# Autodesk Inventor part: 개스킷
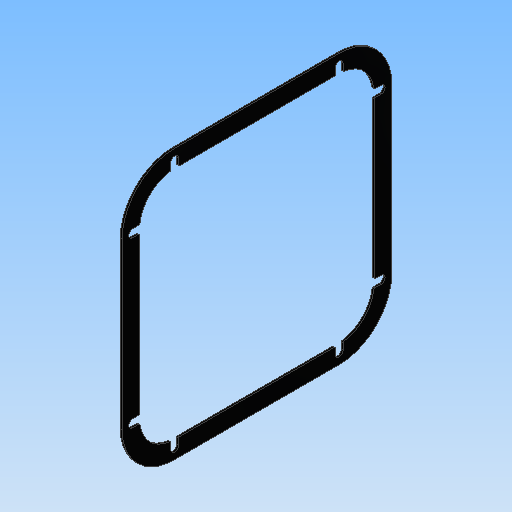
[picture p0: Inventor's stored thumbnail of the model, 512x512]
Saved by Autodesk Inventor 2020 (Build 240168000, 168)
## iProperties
Created: 2022-02
Part Number: 개스킷
Material: 황동, 연질 노란색
Document SubType Name: Modeling
Designer: mdu-edu
Density: 8.47 g/cm^3
Mass: 43.3806 g
Surface Area: 113.92 cm^2
Volume: 5.12167 cm^3
Appearance: 피막 처리 - 검은색
Author: mdu-edu
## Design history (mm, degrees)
sketch "스케치1"
  geometry: L1 (-77, 77)-(77, 77); L2 (77, 77)-(77, -77); L3 (77, -77)-(-77, -77); L4 (-77, -77)-(-77, 77); L5 (-77, 77)-(77, -77); L6 (77, 77)-(-77, -77); 1 further point
  constraints: 12 end point, 2 midpoint, 2 parallel, 2 perpendicular, 1 horizontal
  dimensions: "d1" = 154 distance of L1.end L2.end
extrude "돌출1" new body sketch "스케치1" distance "d2" = 1; taper "d3" = 0 deg
fillet "모깎기1" dims "d4" = 30
sketch "스케치2"
  geometry: L1 (-47, -77)-(47, -77) reference; L2 (77, -47)-(77, 47) reference; L3 (47, 77)-(-47, 77) reference; L4 (-77, 47)-(-77, -47) reference; L5 (67, 47)-(67, -47); L6 (47, -67)-(-47, -67); L7 (-67, -47)-(-67, 47); L8 (-47, 67)-(47, 67); A1 r 30 centre (-47, -47) between (-77, -47) and (-47, -77) reference; A2 r 30 centre (47, -47) between (47, -77) and (77, -47) reference; A3 r 30 centre (47, 47) between (77, 47) and (47, 77) reference; A4 r 30 centre (-47, 47) between (-47, 77) and (-77, 47) reference; A5 r 20 centre (47, 47) between (67, 47) and (47, 67); A6 r 20 centre (47, -47) between (47, -67) and (67, -47); A7 r 20 centre (-47, -47) between (-67, -47) and (-47, -67); A8 r 20 centre (-47, 47) between (-47, 67) and (-67, 47); 1 further point
  constraints: 8 end point, 8 point on circle, 4 centre point, 7 other
  dimensions: "d5" = 10 distance between parallel lines of L2 L5
extrude "돌출2" cut sketch "스케치2" extent not by distance; stored distance "d6" = 1; taper "d7" = 0 deg
sketch "스케치3"
  geometry: L1 (47, 77)-(-47, 77) reference; L2 (77, -47)-(77, 47) reference; L3 (-47, -77)-(47, -77) reference; L4 (-77, 47)-(-77, -47) reference; L5 (-47, 71)-(47, 71); L6 (71, 47)-(71, -47); L7 (47, -71)-(-47, -71); L8 (-71, -47)-(-71, 47); A1 r 30 centre (47, 47) between (77, 47) and (47, 77) reference; A2 r 30 centre (47, -47) between (47, -77) and (77, -47) reference; A3 r 30 centre (-47, -47) between (-77, -47) and (-47, -77) reference; A4 r 30 centre (-47, 47) between (-47, 77) and (-77, 47) reference; A5 r 24 centre (47, 47) between (71, 47) and (47, 71); A6 r 24 centre (47, -47) between (47, -71) and (71, -47); A7 r 24 centre (-47, -47) between (-71, -47) and (-47, -71); A8 r 24 centre (-47, 47) between (-47, 71) and (-71, 47); 9 further points
  constraints: 8 coincident, 8 end point, 8 point on circle, 4 centre point, 7 other
  dimensions: "d8" = 6 distance between parallel lines of L2 L6
hole "구멍1" sketch "스케치3" at (-47, 71), (47, 71), (71, 47), (71, -47), (47, -71), (-47, -71), (-71, -47), (-71, 47) diameter "d9" = 4.5; stored, may be unused: countersink angle "d13" = 90 deg, drill point angle "d15" = 118 deg; dims "d10" = 6, "d11" = 4, "d12" = 2, "d14" = 8
sketch "스케치4"
  geometry: L1 (-47, 67)-(47, 67) reference; L2 (-67, -47)-(-67, 47) reference; L3 (67, 47)-(67, -47) reference; L4 (47, -67)-(-47, -67) reference; L5 (-44.75, 71)-(-44.75, 67); L6 (-49.25, 71)-(-49.25, 66.873); L7 (-71, 49.25)-(-66.873, 49.25); L8 (-71, 44.75)-(-67, 44.75); L9 (0, 0)-(0, 67); L10 (0, 0)-(-67, 0); L11 (49.25, 71)-(49.25, 66.873); L12 (44.75, 71)-(44.75, 67); L13 (71, 49.25)-(66.873, 49.25); L14 (71, 44.75)-(67, 44.75); L15 (-44.75, -71)-(-44.75, -67); L16 (-49.25, -71)-(-49.25, -66.873); L17 (-71, -49.25)-(-66.873, -49.25); L18 (-71, -44.75)-(-67, -44.75); L19 (49.25, -71)-(49.25, -66.873); L20 (44.75, -71)-(44.75, -67); L21 (71, -49.25)-(66.873, -49.25); L22 (71, -44.75)-(67, -44.75); C1 r 2.25 at (47, 71) reference; C2 r 2.25 at (71, 47) reference; C3 r 2.25 at (71, -47) reference; C4 r 2.25 at (47, -71) reference; C5 r 2.25 at (-47, -71) reference; C6 r 2.25 at (-71, -47) reference; A1 r 2.25 centre (-47, 71) between (-44.75, 71) and (-49.25, 71) reference; A2 r 2.25 centre (-71, 47) between (-71, 44.75) and (-71, 49.25) reference; A3 r 20 centre (-47, 47) between (-47, 67) and (-67, 47) reference; A4 r 20 centre (47, 47) between (67, 47) and (47, 67) reference; A5 r 20 centre (47, -47) between (47, -67) and (67, -47) reference; A6 r 20 centre (-47, -47) between (-67, -47) and (-47, -67) reference; A7 r 2.25 centre (-71, 47) between (-71, 49.25) and (-71, 44.75); A8 r 2.25 centre (-47, 71) between (-44.75, 71) and (-49.25, 71)
  constraints: 36 end point, 24 symmetric about line, 10 point on circle, 4 tangent, 2 centre point, 2 coincident, 2 midpoint, 2 perpendicular, 2 point on line, 1 parallel, 1 vertical
extrude "돌출3" cut sketch "스케치4" extent not by distance; stored distance "d16" = 10; taper "d17" = 0 deg
fillet "모깎기2" dims "d18" = 0.5
node "솔리드1"
mirror "대칭1"
mirror "대칭2"
node "투영된 루프1"
